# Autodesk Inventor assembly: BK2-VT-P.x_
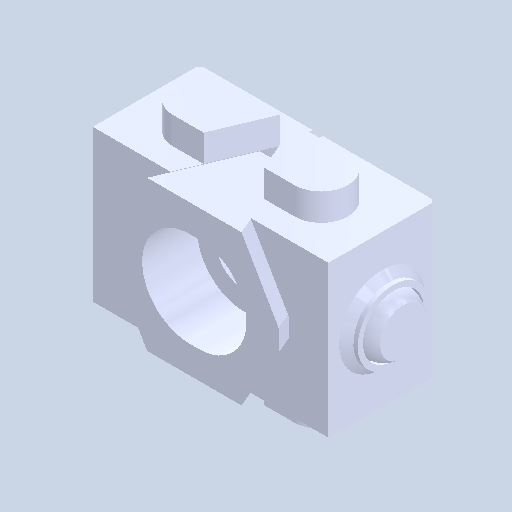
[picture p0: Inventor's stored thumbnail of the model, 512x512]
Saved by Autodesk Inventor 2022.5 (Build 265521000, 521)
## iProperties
Created: 2024-08
Part Number: BK2-VT-P.x_
Document SubType Name: Assembly
Designer: ImaoCorp
Author: ImaoCorp
Sending System: SOLIDWORKS 2022-2022290
MC: AMD64
MC_MODEL: Intel64 Family 6 Model 60 Stepping 3, GenuineIntel
OS: Windows_NT
FRU: Parasolid Version 33.1, build 260,  4-25-2022
FORMAT: text
GUISE: transmit
KEY: FILEBK2-VT-P.x_t
DATE: Fri Aug  2 11:42:15 2024
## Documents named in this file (4)
- X:\14_SW2022-Inv2022\07_2024-10新製品(WHS)\OKV_データ\b\bk2-vt-p\BK2-VT-P.x_.iam
- X:\14_SW2022-Inv2022\07_2024-10新製品(WHS)\OKV_データ\b\bk2-vt-p\BK2-VT-P_01.ipt
- X:\14_SW2022-Inv2022\07_2024-10新製品(WHS)\OKV_データ\b\bk2-vt-p\BK2-VT-P_02.ipt
- X:\14_SW2022-Inv2022\07_2024-10新製品(WHS)\OKV_データ\b\bk2-vt-p\BK2-VT-P_03.ipt
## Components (3 placed, 3 different names)
1. BK2-VT-P_01
2. BK2-VT-P_02
3. BK2-VT-P_03
